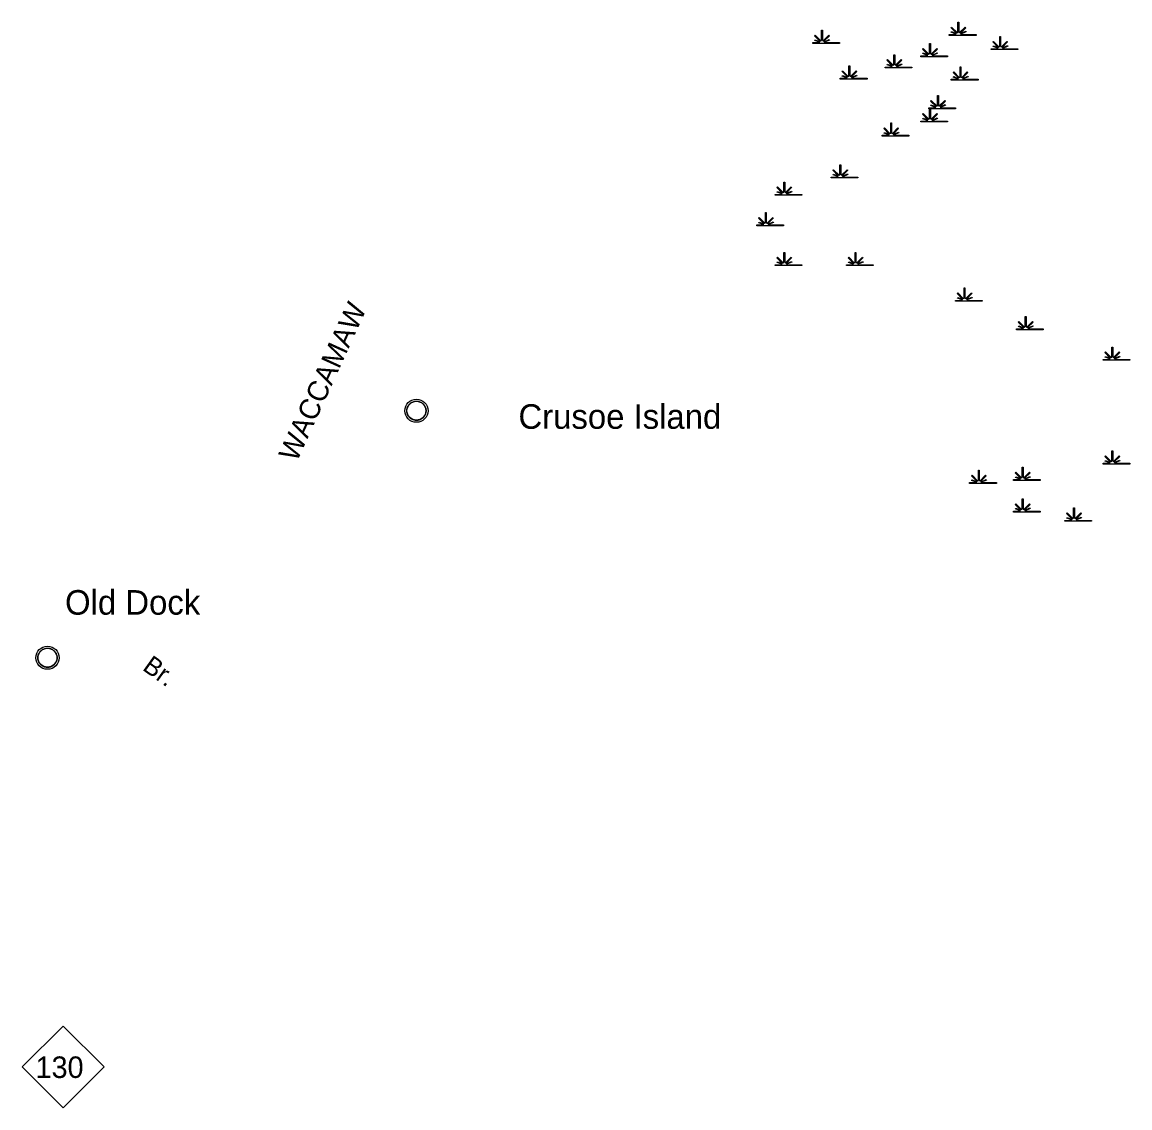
# Model space of a CAD drawing. Extents: x 5197761 to 5514561, y 1890130 to 2080942.
# Drawn here: x 5351825 to 5387878, y 1939103 to 1974448 of the extents above; entities that cross this region are included whole.
import ezdxf

# ---------------------------------------------------------------- set-up
doc = ezdxf.new("R2010")
doc.units = 0
for name, color, linetype in [('Exist Civil Demographics Community CELL', 7, 'Continuous'), ('Exist Civil Demographics Community Label', 7, 'Continuous'), ('Exist Hydrographic Creek Single Shore Label', 7, 'Continuous'), ('Exist Hydrographic River Shore Label', 7, 'Continuous'), ('Exist Hydrographic Swamp CELL', 7, 'Continuous'), ('Exist Road Primary NC Shield CELL', 7, 'Continuous'), ('Exist Road Primary NC Shield Number Label', 7, 'Continuous')]:
    doc.layers.add(name, color=color, linetype=linetype)

msp = doc.modelspace()

# ---------------------------------------------------------------- linework, layer by layer
at = {"layer": 'Exist Civil Demographics Community CELL'}
for points in [[(5364348, 1961847), (5364352, 1961869), (5364359, 1961896), (5364371, 1961924), (5364382, 1961947), (5364396, 1961970), (5364411, 1961991), (5364427, 1962008), (5364445, 1962027), (5364467, 1962045), (5364489, 1962060), (5364508, 1962071), (5364528, 1962081), (5364550, 1962090), (5364573, 1962097), (5364590, 1962102), (5364610, 1962105), (5364626, 1962108), (5364652, 1962109), (5364669, 1962109), (5364692, 1962107), (5364712, 1962105), (5364731, 1962101), (5364751, 1962095), (5364772, 1962087), (5364798, 1962076), (5364823, 1962062), (5364844, 1962047), (5364864, 1962031), (5364878, 1962019), (5364894, 1962001), (5364910, 1961982), (5364922, 1961964), (5364934, 1961944), (5364944, 1961923), (5364952, 1961903), (5364959, 1961883), (5364964, 1961865), (5364968, 1961841), (5364971, 1961822), (5364972, 1961798), (5364971, 1961775), (5364969, 1961752), (5364965, 1961730), (5364958, 1961705), (5364951, 1961682), (5364942, 1961662), (5364929, 1961638), (5364916, 1961617), (5364902, 1961598), (5364885, 1961579), (5364864, 1961559), (5364844, 1961542), (5364824, 1961529), (5364807, 1961519), (5364779, 1961506), (5364751, 1961495), (5364727, 1961489), (5364701, 1961484), (5364683, 1961482), (5364665, 1961481), (5364643, 1961481), (5364625, 1961483), (5364603, 1961486), (5364579, 1961491), (5364561, 1961496), (5364540, 1961503), (5364522, 1961511), (5364506, 1961520), (5364479, 1961537), (5364457, 1961554), (5364437, 1961572), (5364419, 1961591), (5364406, 1961607), (5364394, 1961624), (5364378, 1961652), (5364371, 1961666), (5364364, 1961682), (5364354, 1961715), (5364348, 1961743), (5364345, 1961764), (5364344, 1961789), (5364344, 1961808), (5364346, 1961834)], [(5352340, 1953805), (5352344, 1953828), (5352351, 1953854), (5352363, 1953883), (5352374, 1953906), (5352388, 1953929), (5352403, 1953949), (5352419, 1953967), (5352437, 1953985), (5352459, 1954004), (5352481, 1954018), (5352500, 1954030), (5352521, 1954039), (5352542, 1954049), (5352565, 1954056), (5352582, 1954061), (5352602, 1954063), (5352618, 1954066), (5352644, 1954067), (5352661, 1954067), (5352684, 1954066), (5352704, 1954063), (5352723, 1954059), (5352743, 1954053), (5352764, 1954046), (5352791, 1954034), (5352816, 1954020), (5352836, 1954006), (5352857, 1953990), (5352870, 1953977), (5352886, 1953960), (5352902, 1953941), (5352914, 1953923), (5352927, 1953903), (5352936, 1953882), (5352944, 1953862), (5352951, 1953842), (5352956, 1953823), (5352960, 1953799), (5352963, 1953780), (5352964, 1953756), (5352963, 1953733), (5352961, 1953711), (5352957, 1953689), (5352950, 1953664), (5352943, 1953641), (5352934, 1953620), (5352921, 1953596), (5352908, 1953575), (5352894, 1953556), (5352877, 1953537), (5352856, 1953517), (5352836, 1953501), (5352816, 1953487), (5352799, 1953477), (5352771, 1953464), (5352743, 1953453), (5352719, 1953448), (5352693, 1953442), (5352675, 1953440), (5352657, 1953439), (5352635, 1953439), (5352618, 1953441), (5352595, 1953444), (5352571, 1953449), (5352553, 1953454), (5352532, 1953462), (5352514, 1953470), (5352498, 1953479), (5352471, 1953495), (5352449, 1953512), (5352429, 1953530), (5352411, 1953550), (5352398, 1953565), (5352387, 1953582), (5352370, 1953611), (5352363, 1953625), (5352356, 1953641), (5352346, 1953674), (5352340, 1953702), (5352337, 1953722), (5352336, 1953748), (5352336, 1953766), (5352338, 1953792)]]:
    msp.add_lwpolyline(points, close=True, dxfattribs=at)
for centre, radius in [((5364658, 1961797), 377), ((5364657, 1961798), 307), ((5352650, 1953756), 377), ((5352649, 1953757), 307)]:
    msp.add_circle(centre, radius, dxfattribs=at)
at = {"layer": 'Exist Hydrographic Swamp CELL'}
for points in [[(5382001, 1974046), (5382211, 1974046), (5382219, 1974060), (5382066, 1974120), (5382078, 1974140), (5382229, 1974077), (5382235, 1974089), (5382057, 1974267), (5382078, 1974288), (5382259, 1974106), (5382284, 1974115), (5382284, 1974448), (5382313, 1974448), (5382313, 1974115), (5382338, 1974106), (5382520, 1974288), (5382540, 1974267), (5382362, 1974089), (5382370, 1974075), (5382534, 1974149), (5382544, 1974129), (5382380, 1974058), (5382386, 1974046), (5382871, 1974046), (5382871, 1974017), (5382001, 1974017)], [(5377557, 1973780), (5377768, 1973781), (5377776, 1973795), (5377623, 1973854), (5377634, 1973875), (5377785, 1973812), (5377792, 1973824), (5377614, 1974002), (5377634, 1974022), (5377816, 1973840), (5377841, 1973850), (5377841, 1974182), (5377870, 1974182), (5377870, 1973850), (5377895, 1973840), (5378076, 1974022), (5378097, 1974002), (5377919, 1973824), (5377927, 1973809), (5378091, 1973884), (5378101, 1973864), (5377937, 1973792), (5377943, 1973781), (5378427, 1973780), (5378427, 1973752), (5377557, 1973752)], [(5383360, 1973581), (5383571, 1973582), (5383579, 1973596), (5383426, 1973655), (5383437, 1973676), (5383588, 1973613), (5383594, 1973625), (5383417, 1973803), (5383437, 1973823), (5383618, 1973641), (5383644, 1973651), (5383644, 1973983), (5383673, 1973983), (5383673, 1973651), (5383698, 1973641), (5383879, 1973823), (5383900, 1973803), (5383722, 1973625), (5383730, 1973610), (5383894, 1973685), (5383903, 1973665), (5383739, 1973593), (5383746, 1973582), (5384230, 1973581), (5384230, 1973553), (5383360, 1973553)], [(5381072, 1973349), (5381283, 1973350), (5381291, 1973364), (5381138, 1973423), (5381149, 1973444), (5381300, 1973381), (5381307, 1973393), (5381129, 1973571), (5381149, 1973591), (5381330, 1973409), (5381356, 1973419), (5381356, 1973751), (5381385, 1973751), (5381385, 1973419), (5381410, 1973409), (5381591, 1973591), (5381612, 1973571), (5381434, 1973393), (5381442, 1973378), (5381606, 1973453), (5381615, 1973433), (5381451, 1973361), (5381458, 1973350), (5381942, 1973349), (5381942, 1973321), (5381072, 1973321)], [(5379911, 1972985), (5380122, 1972985), (5380130, 1972999), (5379977, 1973059), (5379989, 1973079), (5380140, 1973016), (5380146, 1973028), (5379968, 1973206), (5379989, 1973227), (5380170, 1973045), (5380195, 1973054), (5380195, 1973387), (5380224, 1973387), (5380224, 1973054), (5380249, 1973045), (5380431, 1973227), (5380451, 1973206), (5380273, 1973028), (5380281, 1973013), (5380445, 1973088), (5380455, 1973068), (5380291, 1972997), (5380297, 1972985), (5380782, 1972985), (5380782, 1972956), (5379911, 1972956)], [(5378452, 1972620), (5378663, 1972620), (5378671, 1972634), (5378518, 1972694), (5378530, 1972715), (5378681, 1972652), (5378687, 1972663), (5378509, 1972841), (5378530, 1972862), (5378711, 1972680), (5378736, 1972689), (5378736, 1973022), (5378765, 1973022), (5378765, 1972689), (5378790, 1972680), (5378972, 1972862), (5378992, 1972841), (5378814, 1972663), (5378822, 1972649), (5378986, 1972723), (5378996, 1972703), (5378832, 1972632), (5378838, 1972620), (5379323, 1972620), (5379323, 1972591), (5378452, 1972591)], [(5382067, 1972587), (5382277, 1972587), (5382285, 1972601), (5382132, 1972661), (5382144, 1972681), (5382295, 1972618), (5382301, 1972630), (5382124, 1972808), (5382144, 1972829), (5382325, 1972647), (5382351, 1972656), (5382351, 1972989), (5382380, 1972989), (5382379, 1972656), (5382405, 1972647), (5382586, 1972829), (5382607, 1972808), (5382429, 1972630), (5382437, 1972616), (5382600, 1972690), (5382610, 1972670), (5382446, 1972599), (5382453, 1972587), (5382937, 1972587), (5382937, 1972558), (5382067, 1972558)], [(5381337, 1971658), (5381548, 1971658), (5381556, 1971673), (5381403, 1971732), (5381414, 1971753), (5381565, 1971690), (5381572, 1971702), (5381394, 1971880), (5381415, 1971900), (5381596, 1971718), (5381621, 1971728), (5381621, 1972060), (5381650, 1972060), (5381650, 1971728), (5381675, 1971718), (5381857, 1971900), (5381877, 1971880), (5381699, 1971702), (5381707, 1971687), (5381871, 1971762), (5381881, 1971741), (5381717, 1971670), (5381723, 1971658), (5382207, 1971658), (5382207, 1971630), (5381337, 1971630)], [(5381072, 1971227), (5381283, 1971227), (5381291, 1971242), (5381138, 1971301), (5381149, 1971322), (5381300, 1971259), (5381307, 1971270), (5381129, 1971449), (5381149, 1971469), (5381330, 1971287), (5381356, 1971297), (5381356, 1971629), (5381385, 1971629), (5381385, 1971297), (5381410, 1971287), (5381591, 1971469), (5381612, 1971449), (5381434, 1971270), (5381442, 1971256), (5381606, 1971330), (5381615, 1971310), (5381451, 1971239), (5381458, 1971227), (5381942, 1971227), (5381942, 1971199), (5381072, 1971199)], [(5379812, 1970763), (5380023, 1970763), (5380031, 1970778), (5379878, 1970837), (5379889, 1970858), (5380040, 1970795), (5380046, 1970806), (5379869, 1970984), (5379889, 1971005), (5380070, 1970823), (5380096, 1970833), (5380096, 1971165), (5380125, 1971165), (5380125, 1970833), (5380150, 1970823), (5380331, 1971005), (5380352, 1970984), (5380174, 1970806), (5380182, 1970792), (5380346, 1970866), (5380355, 1970846), (5380191, 1970775), (5380198, 1970763), (5380682, 1970763), (5380682, 1970734), (5379812, 1970734)], [(5378154, 1969403), (5378365, 1969404), (5378373, 1969418), (5378220, 1969477), (5378231, 1969498), (5378382, 1969435), (5378388, 1969447), (5378211, 1969625), (5378231, 1969645), (5378412, 1969463), (5378438, 1969473), (5378438, 1969805), (5378467, 1969805), (5378467, 1969473), (5378492, 1969463), (5378673, 1969645), (5378694, 1969625), (5378516, 1969447), (5378524, 1969432), (5378688, 1969507), (5378697, 1969487), (5378533, 1969415), (5378540, 1969404), (5379024, 1969403), (5379024, 1969375), (5378154, 1969375)], [(5376330, 1968840), (5376541, 1968840), (5376549, 1968854), (5376396, 1968914), (5376407, 1968934), (5376558, 1968872), (5376565, 1968883), (5376387, 1969061), (5376408, 1969082), (5376589, 1968900), (5376614, 1968909), (5376614, 1969242), (5376643, 1969242), (5376643, 1968909), (5376668, 1968900), (5376849, 1969082), (5376870, 1969061), (5376692, 1968883), (5376700, 1968869), (5376864, 1968943), (5376874, 1968923), (5376710, 1968852), (5376716, 1968840), (5377200, 1968840), (5377200, 1968811), (5376330, 1968811)], [(5375733, 1967845), (5375944, 1967845), (5375952, 1967860), (5375799, 1967919), (5375811, 1967940), (5375961, 1967877), (5375968, 1967888), (5375790, 1968066), (5375811, 1968087), (5375992, 1967905), (5376017, 1967915), (5376017, 1968247), (5376046, 1968247), (5376046, 1967915), (5376071, 1967905), (5376253, 1968087), (5376273, 1968066), (5376095, 1967888), (5376103, 1967874), (5376267, 1967948), (5376277, 1967928), (5376113, 1967857), (5376119, 1967845), (5376603, 1967845), (5376603, 1967816), (5375733, 1967816)], [(5376330, 1966552), (5376541, 1966552), (5376549, 1966566), (5376396, 1966626), (5376407, 1966646), (5376558, 1966584), (5376565, 1966595), (5376387, 1966773), (5376408, 1966794), (5376589, 1966612), (5376614, 1966621), (5376614, 1966954), (5376643, 1966954), (5376643, 1966621), (5376668, 1966612), (5376849, 1966794), (5376870, 1966773), (5376692, 1966595), (5376700, 1966581), (5376864, 1966655), (5376874, 1966635), (5376710, 1966564), (5376716, 1966552), (5377200, 1966552), (5377200, 1966523), (5376330, 1966523)], [(5378651, 1966552), (5378862, 1966552), (5378870, 1966566), (5378717, 1966626), (5378729, 1966646), (5378879, 1966584), (5378886, 1966595), (5378708, 1966773), (5378729, 1966794), (5378910, 1966612), (5378935, 1966621), (5378935, 1966954), (5378964, 1966954), (5378964, 1966621), (5378989, 1966612), (5379171, 1966794), (5379191, 1966773), (5379013, 1966595), (5379021, 1966581), (5379185, 1966655), (5379195, 1966635), (5379031, 1966564), (5379037, 1966552), (5379521, 1966552), (5379521, 1966523), (5378651, 1966523)], [(5382199, 1965391), (5382410, 1965391), (5382418, 1965406), (5382265, 1965465), (5382277, 1965486), (5382428, 1965423), (5382434, 1965434), (5382256, 1965613), (5382277, 1965633), (5382458, 1965451), (5382483, 1965461), (5382483, 1965793), (5382512, 1965793), (5382512, 1965461), (5382537, 1965451), (5382719, 1965633), (5382739, 1965613), (5382561, 1965434), (5382569, 1965420), (5382733, 1965494), (5382743, 1965474), (5382579, 1965403), (5382585, 1965391), (5383070, 1965391), (5383070, 1965363), (5382199, 1965363)], [(5384189, 1964463), (5384400, 1964463), (5384408, 1964477), (5384255, 1964537), (5384266, 1964557), (5384417, 1964494), (5384423, 1964506), (5384246, 1964684), (5384266, 1964705), (5384447, 1964523), (5384473, 1964532), (5384473, 1964865), (5384502, 1964865), (5384502, 1964532), (5384527, 1964523), (5384708, 1964705), (5384729, 1964684), (5384551, 1964506), (5384559, 1964492), (5384723, 1964566), (5384732, 1964546), (5384568, 1964475), (5384575, 1964463), (5385059, 1964463), (5385059, 1964434), (5384189, 1964434)], [(5387008, 1963468), (5387218, 1963468), (5387226, 1963483), (5387073, 1963542), (5387085, 1963563), (5387236, 1963500), (5387242, 1963511), (5387064, 1963689), (5387085, 1963710), (5387266, 1963528), (5387291, 1963538), (5387291, 1963870), (5387320, 1963870), (5387320, 1963538), (5387345, 1963528), (5387527, 1963710), (5387547, 1963689), (5387370, 1963511), (5387378, 1963497), (5387541, 1963571), (5387551, 1963551), (5387387, 1963480), (5387393, 1963468), (5387878, 1963468), (5387878, 1963439), (5387008, 1963439)], [(5387008, 1960086), (5387218, 1960086), (5387226, 1960100), (5387073, 1960160), (5387085, 1960180), (5387236, 1960117), (5387242, 1960129), (5387064, 1960307), (5387085, 1960328), (5387266, 1960146), (5387291, 1960155), (5387291, 1960488), (5387320, 1960488), (5387320, 1960155), (5387345, 1960146), (5387527, 1960328), (5387547, 1960307), (5387370, 1960129), (5387378, 1960115), (5387541, 1960189), (5387551, 1960169), (5387387, 1960098), (5387393, 1960086), (5387878, 1960086), (5387878, 1960057), (5387008, 1960057)], [(5382664, 1959456), (5382874, 1959456), (5382882, 1959470), (5382729, 1959530), (5382741, 1959550), (5382892, 1959487), (5382898, 1959499), (5382720, 1959677), (5382741, 1959698), (5382922, 1959516), (5382947, 1959525), (5382947, 1959858), (5382976, 1959858), (5382976, 1959525), (5383002, 1959516), (5383183, 1959698), (5383203, 1959677), (5383026, 1959499), (5383034, 1959485), (5383197, 1959559), (5383207, 1959539), (5383043, 1959468), (5383050, 1959456), (5383534, 1959456), (5383534, 1959427), (5382664, 1959427)], [(5384090, 1959555), (5384300, 1959555), (5384308, 1959570), (5384155, 1959629), (5384167, 1959650), (5384318, 1959587), (5384324, 1959598), (5384146, 1959777), (5384167, 1959797), (5384348, 1959615), (5384373, 1959625), (5384373, 1959957), (5384402, 1959957), (5384402, 1959625), (5384427, 1959615), (5384609, 1959797), (5384629, 1959777), (5384452, 1959598), (5384460, 1959584), (5384623, 1959658), (5384633, 1959638), (5384469, 1959567), (5384475, 1959555), (5384960, 1959555), (5384960, 1959527), (5384090, 1959527)], [(5384090, 1958527), (5384300, 1958527), (5384308, 1958542), (5384155, 1958601), (5384167, 1958622), (5384318, 1958559), (5384324, 1958571), (5384146, 1958749), (5384167, 1958769), (5384348, 1958587), (5384373, 1958597), (5384373, 1958929), (5384402, 1958929), (5384402, 1958597), (5384427, 1958587), (5384609, 1958769), (5384629, 1958749), (5384452, 1958571), (5384460, 1958556), (5384623, 1958631), (5384633, 1958610), (5384469, 1958539), (5384475, 1958527), (5384960, 1958527), (5384960, 1958499), (5384090, 1958499)], [(5385764, 1958229), (5385975, 1958229), (5385983, 1958243), (5385830, 1958303), (5385841, 1958324), (5385992, 1958261), (5385999, 1958272), (5385821, 1958450), (5385841, 1958471), (5386022, 1958289), (5386048, 1958298), (5386048, 1958631), (5386077, 1958631), (5386077, 1958298), (5386102, 1958289), (5386283, 1958471), (5386304, 1958450), (5386126, 1958272), (5386134, 1958258), (5386298, 1958332), (5386307, 1958312), (5386143, 1958241), (5386150, 1958229), (5386634, 1958229), (5386634, 1958200), (5385764, 1958200)]]:
    msp.add_lwpolyline(points, close=True, dxfattribs=at)
at = {"layer": 'Exist Road Primary NC Shield CELL'}
msp.add_lwpolyline([(5351825, 1940435), (5353157, 1941767), (5354489, 1940435), (5353157, 1939103)], close=True, dxfattribs=at)

# ---------------------------------------------------------------- texts
at = {"layer": 'Exist Civil Demographics Community Label'}
for s, p in [('Crusoe Island', (5367979, 1961209)), ('Old Dock', (5353221, 1955158))]:
    msp.add_text(s, height=800, dxfattribs=at).set_placement(p)
at = {"layer": 'Exist Hydrographic Creek Single Shore Label'}
msp.add_text('Br.', height=600, rotation=324.3767, dxfattribs=at).set_placement((5355710, 1953379))
at = {"layer": 'Exist Hydrographic River Shore Label'}
msp.add_text('WACCAMAW', height=669.3, rotation=65.5065, dxfattribs=at).set_placement((5360759, 1960099))
at = {"layer": 'Exist Road Primary NC Shield Number Label'}
msp.add_text('130', height=700, dxfattribs=at).set_placement((5352262, 1940076))

doc.saveas('drawing.dxf')
